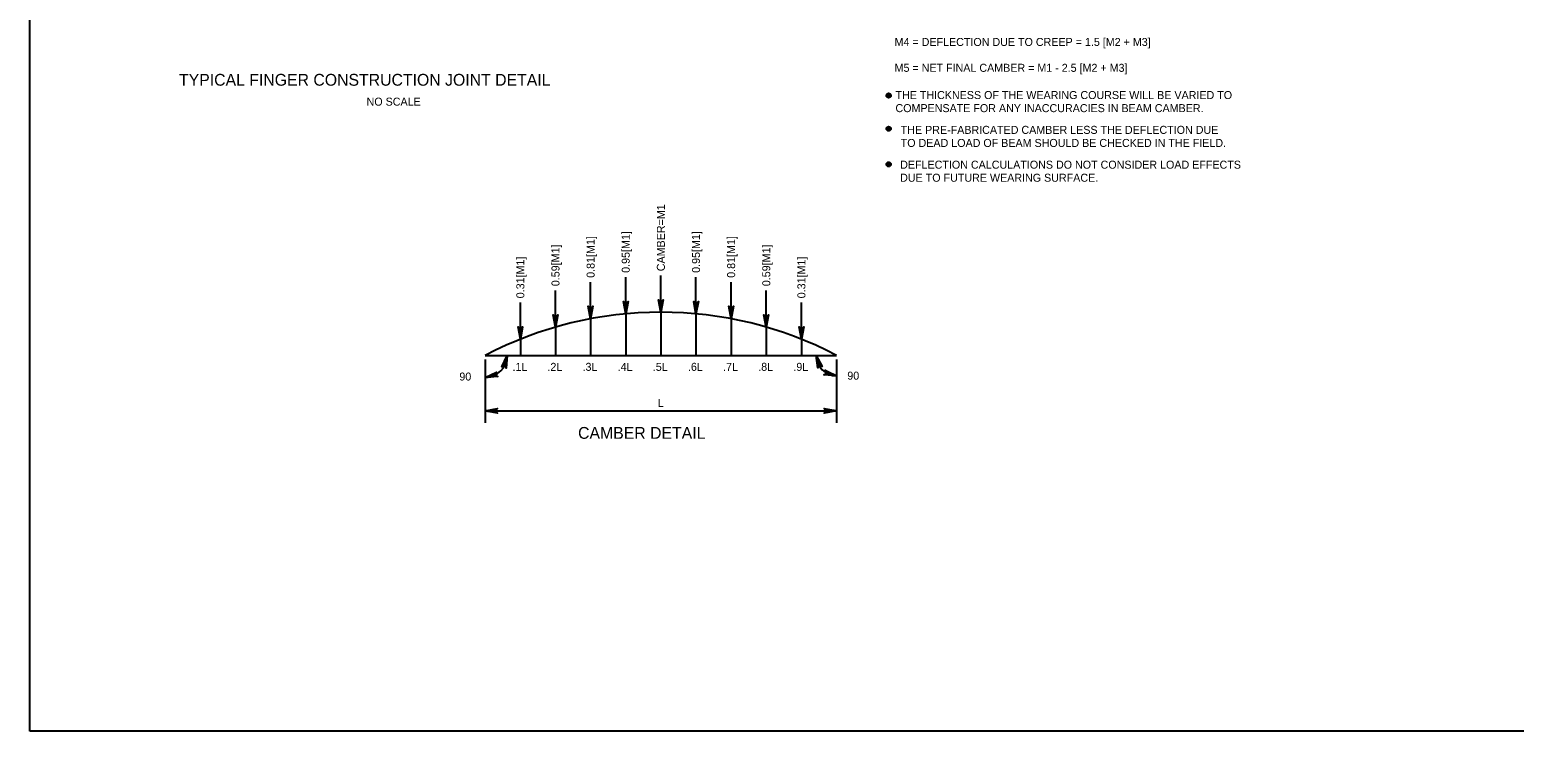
# Model space of a CAD drawing. Extents: x 638263 to 640360, y 293683 to 298655.
# Drawn here: x 639316 to 639873, y 296668 to 296931 of the extents above; entities that cross this region are included whole.
import ezdxf

# ---------------------------------------------------------------- set-up
doc = ezdxf.new("R2010")
doc.units = 0
for name, color, linetype in [('2', 7, 'Continuous'), ('4', 7, 'Continuous'), ('5', 7, 'Continuous'), ('8', 7, 'Continuous')]:
    doc.layers.add(name, color=color, linetype=linetype)

msp = doc.modelspace()

# ---------------------------------------------------------------- linework, layer by layer
at = {"layer": '2'}
for p, q in [((639316.46, 296668.46), (639316.46, 297232.46)), ((639487.16, 296809.25), (639618.83, 296809.25)), ((640102.46, 296668.46), (639316.46, 296668.46))]:
    msp.add_line(p, q, dxfattribs=at)
at = {"layer": '4'}
for p, q in [((639526.66, 296822.98), (639526.66, 296809.25)), ((639539.83, 296824.84), (639539.83, 296809.25)), ((639553, 296825.45), (639553, 296809.25)), ((639566.16, 296824.84), (639566.16, 296809.25)), ((639579.33, 296822.98), (639579.33, 296809.25)), ((639513.5, 296819.84), (639513.5, 296809.25)), ((639592.5, 296819.84), (639592.5, 296809.25)), ((639500.33, 296815.31), (639500.33, 296809.25)), ((639605.66, 296815.31), (639605.66, 296809.25)), ((639500.33, 296809.25), (639500.33, 296809.25)), ((639513.5, 296809.25), (639513.5, 296809.25)), ((639526.66, 296809.25), (639526.66, 296809.25)), ((639539.83, 296809.25), (639539.83, 296809.25)), ((639553, 296809.25), (639553, 296809.25)), ((639566.16, 296809.25), (639566.16, 296809.25)), ((639579.33, 296809.25), (639579.33, 296809.25)), ((639592.5, 296809.25), (639592.5, 296809.25)), ((639605.66, 296809.25), (639605.66, 296809.25))]:
    msp.add_line(p, q, dxfattribs=at)
msp.add_arc((639553, 296683.59), 141.86, 62.3509, 117.6491, dxfattribs=at)
at = {"layer": '5'}
for p, q in [((639539.83, 296824.84), (639539.83, 296838.55)), ((639553, 296825.45), (639553, 296839.16)), ((639566.16, 296824.84), (639566.16, 296838.55)), ((639513.5, 296819.84), (639513.5, 296833.55)), ((639526.66, 296822.98), (639526.66, 296836.69)), ((639579.33, 296822.98), (639579.33, 296836.69)), ((639592.5, 296819.84), (639592.5, 296833.55)), ((639500.33, 296815.31), (639500.33, 296829.02)), ((639605.66, 296815.31), (639605.66, 296829.02)), ((639487.16, 296807.69), (639487.16, 296783.99)), ((639618.83, 296807.69), (639618.83, 296783.99)), ((639487.16, 296788.49), (639618.83, 296788.49))]:
    msp.add_line(p, q, dxfattribs=at)
for points in [[(639526.66, 296822.98), (639525.79, 296827.64), (639526.04, 296827.29), (639526.35, 296827.1), (639526.66, 296827.05), (639526.98, 296827.1), (639527.29, 296827.29), (639527.54, 296827.64), (639526.66, 296822.98), (639527.29, 296827.29), (639526.98, 296827.1), (639526.66, 296822.98), (639526.66, 296827.05), (639526.35, 296827.1), (639526.66, 296822.98), (639526.04, 296827.29)], [(639539.83, 296824.84), (639538.96, 296829.5), (639539.21, 296829.14), (639539.52, 296828.95), (639539.83, 296828.9), (639540.14, 296828.95), (639540.46, 296829.14), (639540.7, 296829.5), (639539.83, 296824.84), (639540.46, 296829.14), (639540.14, 296828.95), (639539.83, 296824.84), (639539.83, 296828.9), (639539.52, 296828.95), (639539.83, 296824.84), (639539.21, 296829.14)], [(639553, 296825.45), (639552.12, 296830.11), (639552.37, 296829.75), (639552.69, 296829.57), (639553, 296829.51), (639553.31, 296829.57), (639553.62, 296829.75), (639553.87, 296830.11), (639553, 296825.45), (639553.62, 296829.75), (639553.31, 296829.57), (639553, 296825.45), (639553, 296829.51), (639552.69, 296829.57), (639553, 296825.45), (639552.37, 296829.75)], [(639566.16, 296824.84), (639565.29, 296829.5), (639565.54, 296829.14), (639565.85, 296828.95), (639566.16, 296828.9), (639566.48, 296828.95), (639566.79, 296829.14), (639567.04, 296829.5), (639566.16, 296824.84), (639566.79, 296829.14), (639566.48, 296828.95), (639566.16, 296824.84), (639566.16, 296828.9), (639565.85, 296828.95), (639566.16, 296824.84), (639565.54, 296829.14)], [(639579.33, 296822.98), (639578.46, 296827.64), (639578.71, 296827.29), (639579.02, 296827.1), (639579.33, 296827.05), (639579.64, 296827.1), (639579.96, 296827.29), (639580.2, 296827.64), (639579.33, 296822.98), (639579.96, 296827.29), (639579.64, 296827.1), (639579.33, 296822.98), (639579.33, 296827.05), (639579.02, 296827.1), (639579.33, 296822.98), (639578.71, 296827.29)], [(639513.5, 296819.84), (639512.62, 296824.5), (639512.87, 296824.14), (639513.19, 296823.96), (639513.5, 296823.9), (639513.81, 296823.96), (639514.12, 296824.14), (639514.37, 296824.5), (639513.5, 296819.84), (639514.12, 296824.14), (639513.81, 296823.96), (639513.5, 296819.84), (639513.5, 296823.9), (639513.19, 296823.96), (639513.5, 296819.84), (639512.87, 296824.14)], [(639592.5, 296819.84), (639591.63, 296824.5), (639591.87, 296824.14), (639592.19, 296823.96), (639592.5, 296823.9), (639592.81, 296823.96), (639593.12, 296824.14), (639593.37, 296824.5), (639592.5, 296819.84), (639593.12, 296824.14), (639592.81, 296823.96), (639592.5, 296819.84), (639592.5, 296823.9), (639592.19, 296823.96), (639592.5, 296819.84), (639591.87, 296824.14)], [(639500.33, 296815.31), (639499.46, 296819.97), (639499.71, 296819.61), (639500.02, 296819.43), (639500.33, 296819.37), (639500.64, 296819.43), (639500.96, 296819.61), (639501.2, 296819.97), (639500.33, 296815.31), (639500.96, 296819.61), (639500.64, 296819.43), (639500.33, 296815.31), (639500.33, 296819.37), (639500.02, 296819.43), (639500.33, 296815.31), (639499.71, 296819.61)], [(639605.66, 296815.31), (639604.79, 296819.97), (639605.04, 296819.61), (639605.35, 296819.43), (639605.66, 296819.37), (639605.98, 296819.43), (639606.29, 296819.61), (639606.54, 296819.97), (639605.66, 296815.31), (639606.29, 296819.61), (639605.98, 296819.43), (639605.66, 296815.31), (639605.66, 296819.37), (639605.35, 296819.43), (639605.66, 296815.31), (639605.04, 296819.61)], [(639495.45, 296809.24), (639495.07, 296804.52), (639494.92, 296804.93), (639494.67, 296805.19), (639494.39, 296805.32), (639494.07, 296805.35), (639493.72, 296805.26), (639493.39, 296804.97), (639495.45, 296809.24), (639493.72, 296805.26), (639494.07, 296805.35), (639495.45, 296809.24), (639494.39, 296805.32), (639494.67, 296805.19), (639495.45, 296809.24), (639494.92, 296804.93)], [(639611.21, 296809.25), (639613.45, 296805.06), (639613.1, 296805.33), (639612.75, 296805.42), (639612.43, 296805.37), (639612.15, 296805.23), (639611.91, 296804.96), (639611.78, 296804.54), (639611.21, 296809.25), (639611.91, 296804.96), (639612.15, 296805.23), (639611.21, 296809.25), (639612.43, 296805.37), (639612.75, 296805.42), (639611.21, 296809.25), (639613.1, 296805.33)], [(639487.17, 296800.98), (639491.46, 296803), (639491.17, 296802.67), (639491.07, 296802.32), (639491.1, 296802.01), (639491.23, 296801.72), (639491.49, 296801.46), (639491.9, 296801.31), (639487.17, 296800.98), (639491.49, 296801.46), (639491.23, 296801.72), (639487.17, 296800.98), (639491.1, 296802.01), (639491.07, 296802.32), (639487.17, 296800.98), (639491.17, 296802.67)], [(639618.82, 296801.58), (639614.1, 296802.04), (639614.52, 296802.18), (639614.78, 296802.43), (639614.92, 296802.71), (639614.96, 296803.03), (639614.87, 296803.38), (639614.59, 296803.72), (639618.82, 296801.58), (639614.87, 296803.38), (639614.96, 296803.03), (639618.82, 296801.58), (639614.92, 296802.71), (639614.78, 296802.43), (639618.82, 296801.58), (639614.52, 296802.18)], [(639487.16, 296788.49), (639491.82, 296789.36), (639491.47, 296789.11), (639491.28, 296788.8), (639491.23, 296788.49), (639491.28, 296788.18), (639491.47, 296787.86), (639491.82, 296787.62), (639487.16, 296788.49), (639491.47, 296787.86), (639491.28, 296788.18), (639487.16, 296788.49), (639491.23, 296788.49), (639491.28, 296788.8), (639487.16, 296788.49), (639491.47, 296789.11)], [(639618.83, 296788.49), (639614.17, 296787.62), (639614.53, 296787.86), (639614.71, 296788.18), (639614.77, 296788.49), (639614.71, 296788.8), (639614.53, 296789.11), (639614.17, 296789.36), (639618.83, 296788.49), (639614.53, 296789.11), (639614.71, 296788.8), (639618.83, 296788.49), (639614.77, 296788.49), (639614.71, 296788.18), (639618.83, 296788.49), (639614.53, 296787.86)]]:
    msp.add_lwpolyline(points, dxfattribs=at)
for centre, radius in [((639638.36, 296906.6), 0.833), ((639638.36, 296906.6), 0.417), ((639638.36, 296894.16), 0.833), ((639638.36, 296894.16), 0.417), ((639638.36, 296880.84), 0.833), ((639638.36, 296880.84), 0.417)]:
    msp.add_circle(centre, radius, dxfattribs=at)
for centre, radius, start, end in [((639487.16, 296809.25), 8.24, 269.9999, 359.9946), ((639618.83, 296809.25), 7.62, 180.0058, 270.0052)]:
    msp.add_arc(centre, radius, start, end, dxfattribs=at)

# ---------------------------------------------------------------- texts
for s, height, p in [('M4 = DEFLECTION DUE TO CREEP = 1.5 [M2 + M3]', 3, (639640.59, 296925.17)), ('M5 = NET FINAL CAMBER = M1 - 2.5 [M2 + M3]', 3, (639640.59, 296915.48)), ('NO SCALE', 3, (639442.71, 296902.81)), (' THE THICKNESS OF THE WEARING COURSE WILL BE VARIED TO', 3, (639639.8, 296905.28)), (' COMPENSATE FOR ANY INACCURACIES IN BEAM CAMBER.', 3, (639639.8, 296900.38)), ('THE PRE-FABRICATED CAMBER LESS THE DEFLECTION DUE', 3, (639642.88, 296892.24)), ('TO DEAD LOAD OF BEAM SHOULD BE CHECKED IN THE FIELD.', 3, (639642.88, 296887.34)), ('DEFLECTION CALCULATIONS DO NOT CONSIDER LOAD EFFECTS', 3, (639642.67, 296879.2)), ('DUE TO FUTURE WEARING SURFACE.', 3, (639642.67, 296874.31)), ('.1L', 3, (639497.4, 296803.47)), ('.2L', 3, (639510.48, 296803.47)), ('.3L', 3, (639523.65, 296803.47)), ('.4L', 3, (639536.81, 296803.47)), ('.5L', 3, (639549.98, 296803.47)), ('.6L', 3, (639563.15, 296803.47)), ('.7L', 3, (639576.31, 296803.47)), ('.8L', 3, (639589.48, 296803.47)), ('.9L', 3, (639602.65, 296803.47)), ('90', 3, (639477.48, 296799.84)), ('90', 3, (639622.87, 296800.17)), ('L', 3, (639551.84, 296789.96)), ('CAMBER DETAIL', 4.4292, (639521.97, 296778.01))]:
    msp.add_text(s, height=height, dxfattribs=at).set_placement(p)
for s, p in [('CAMBER=M1', (639554.5, 296840.79)), ('0.95[M1]', (639541.33, 296840.18)), ('0.95[M1]', (639567.66, 296840.18)), ('0.59[M1]', (639515, 296835.18)), ('0.81[M1]', (639528.17, 296838.32)), ('0.81[M1]', (639580.83, 296838.32)), ('0.59[M1]', (639594, 296835.18)), ('0.31[M1]', (639501.83, 296830.65)), ('0.31[M1]', (639607.16, 296830.65))]:
    msp.add_text(s, height=3, rotation=90, dxfattribs=at).set_placement(p)
at = {"layer": '8'}
msp.add_text('TYPICAL FINGER CONSTRUCTION JOINT DETAIL', height=4.4292, dxfattribs=at).set_placement((639372.42, 296910.28))

doc.saveas('drawing.dxf')
